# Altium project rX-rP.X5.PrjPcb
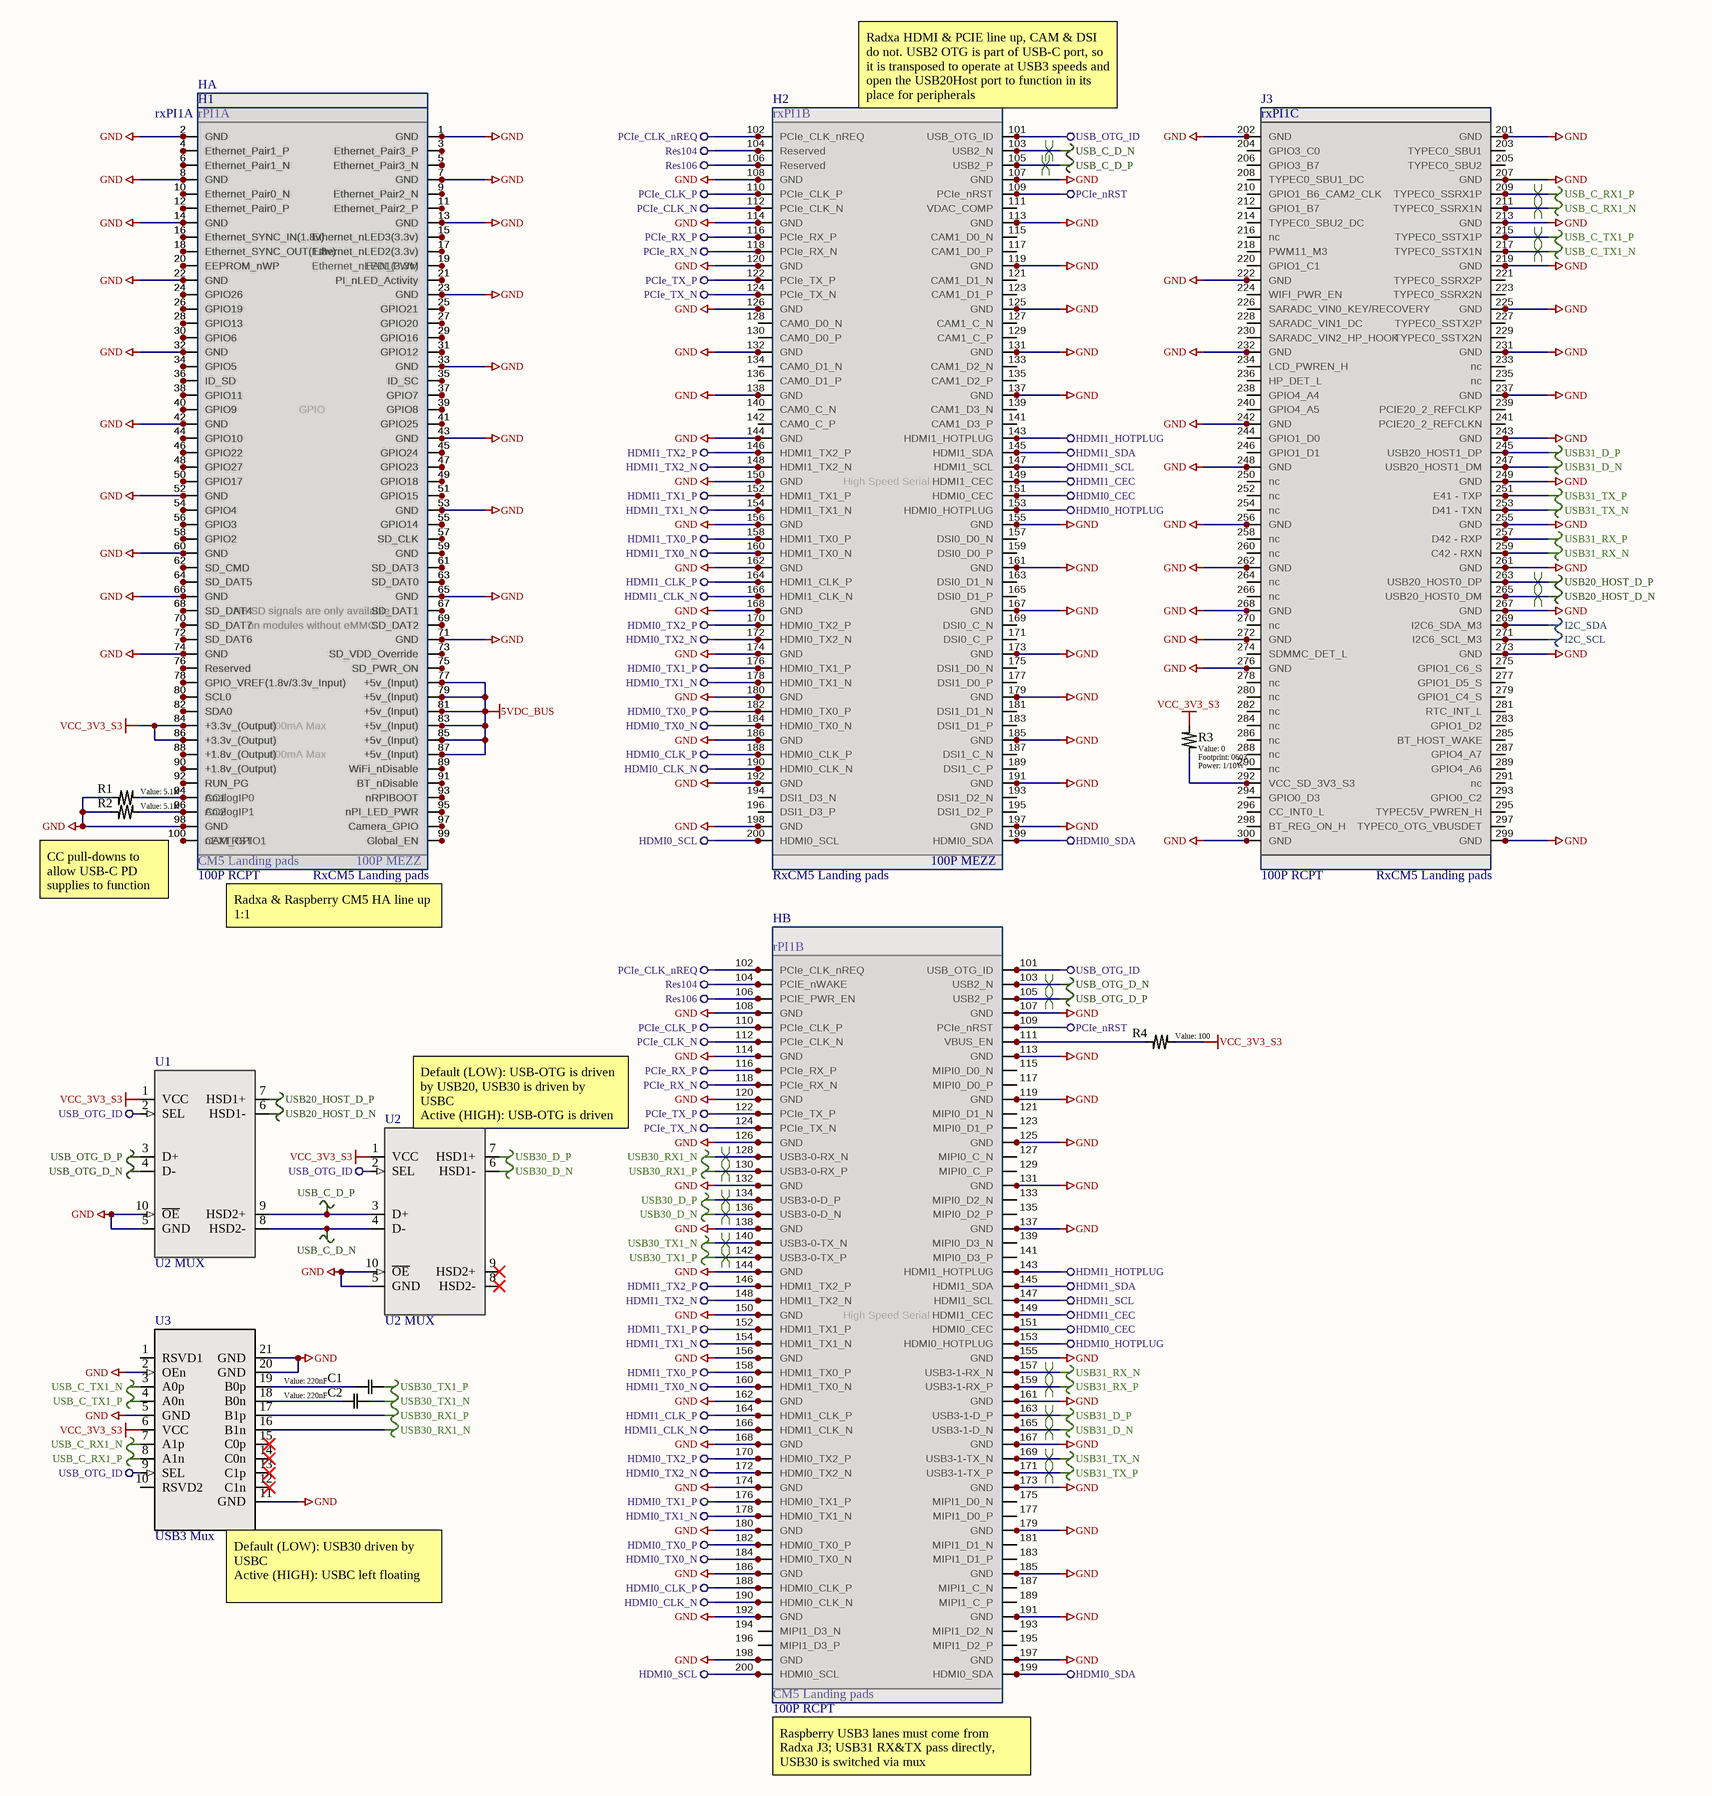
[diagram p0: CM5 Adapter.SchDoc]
1 sheet, 16 parts. Net scope: global (net labels, ports and power ports of the same name join across sheets).
Board file: CM5_Adapter.PcbDoc

## Sheet CM5 Adapter.SchDoc
size C; SheetNumber: 1; SheetTotal: 1

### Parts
C1  value 220nF  [0603]  (hidden comment: Generic Capacitor)
C2  value 220nF  [0603]  (hidden comment: Generic Capacitor)
H1  100P RCPT  [DF40C-100DS-0.4V(51)]
H2  100P MEZZ  [DF40C-100DS-0.4V(51)]
HA  100P MEZZ  [DF40C-100DP-0.4V(51)]
HB  100P RCPT  [DF40C-100DP-0.4V(51)]
J3  100P RCPT  [DF40C-100DS-0.4V(51)]
R1  value 5.1K  [0603]  (hidden comment: Generic Resistor)
R2  value 5.1K  [0603]  (hidden comment: Generic Resistor)
R3  value 0  Power: 1/10W  [0603]  (hidden comment: Generic Resistor)
R4  value 100  [0603]  (hidden comment: Generic Resistor)
rPI1  CM5 Landing pads  [rP-200P-CM-REP (top)]  (parts A,B of 2)
rxPI1  RxCM5 Landing pads  [RX-300P-CM-FTPD]  (parts A,B,C of 3)
U1  U2 MUX  [MSOP-10]
U2  U2 MUX  [MSOP-10]
U3  USB3 Mux  [QFN50P450X250X100-21N]

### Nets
5VDC_BUS: H1.77 H1.79 H1.81 H1.83 H1.85 H1.87 HA.78 HA.80 HA.82 HA.84 HA.86 HA.88 rPI1.77(+5v_(Input)) rPI1.79(+5v_(Input)) rPI1.81(+5v_(Input)) rPI1.83(+5v_(Input)) rPI1.85(+5v_(Input)) rPI1.87(+5v_(Input)) rxPI1.77(+5v_(Input)) rxPI1.79(+5v_(Input)) rxPI1.81(+5v_(Input)) rxPI1.83(+5v_(Input)) rxPI1.85(+5v_(Input)) rxPI1.87(+5v_(Input))
GND: H1.1 H1.2 H1.7 H1.8 H1.13 H1.14 H1.22 H1.23 H1.32 H1.33 H1.42 H1.43 H1.52 H1.53 H1.60 H1.65 H1.66 H1.71 H1.74 H1.98 H2.7 H2.8 H2.13 H2.14 H2.19 H2.20 H2.25 H2.26 H2.31 H2.32 H2.37 H2.38 H2.44 H2.50 H2.55 H2.56 H2.61 H2.62 H2.67 H2.68 H2.73 H2.74 H2.79 H2.80 H2.85 H2.86 H2.91 H2.92 H2.97 H2.98 HA.1 HA.2 HA.7 HA.8 HA.13 HA.14 HA.21 HA.24 HA.31 HA.34 HA.41 HA.44 HA.51 HA.54 HA.59 HA.65 HA.66 HA.72 HA.73 HA.97 HB.7 HB.8 HB.13 HB.14 HB.19 HB.20 HB.25 HB.26 HB.31 HB.32 HB.37 HB.38 HB.43 HB.49 HB.55 HB.56 HB.61 HB.62 HB.67 HB.68 HB.73 HB.74 HB.79 HB.80 HB.85 HB.86 HB.91 HB.92 HB.97 HB.98 J3.1 J3.2 J3.8 J3.14 J3.20 J3.21 J3.26 J3.31 J3.32 J3.38 J3.41 J3.44 J3.47 J3.50 J3.55 J3.56 J3.61 J3.62 J3.67 J3.68 J3.71 J3.74 J3.75 J3.99 J3.100 R1.2 R2.2 rPI1.1(GND) rPI1.2(GND) rPI1.7(GND) rPI1.8(GND) rPI1.13(GND) rPI1.14(GND) rPI1.22(GND) rPI1.23(GND) rPI1.32(GND) rPI1.33(GND) rPI1.42(GND) rPI1.43(GND) rPI1.52(GND) rPI1.53(GND) rPI1.60(GND) rPI1.65(GND) rPI1.66(GND) rPI1.71(GND) rPI1.74(GND) rPI1.98(GND) rPI1.107(GND) rPI1.108(GND) rPI1.113(GND) rPI1.114(GND) rPI1.119(GND) rPI1.120(GND) rPI1.125(GND) rPI1.126(GND) rPI1.131(GND) rPI1.132(GND) rPI1.137(GND) rPI1.138(GND) rPI1.144(GND) rPI1.150(GND) rPI1.155(GND) rPI1.156(GND) rPI1.161(GND) rPI1.162(GND) rPI1.167(GND) rPI1.168(GND) rPI1.173(GND) rPI1.174(GND) rPI1.179(GND) rPI1.180(GND) rPI1.185(GND) rPI1.186(GND) rPI1.191(GND) rPI1.192(GND) rPI1.197(GND) rPI1.198(GND) rxPI1.1(GND) rxPI1.2(GND) rxPI1.7(GND) rxPI1.8(GND) rxPI1.13(GND) rxPI1.14(GND) rxPI1.22(GND) rxPI1.23(GND) rxPI1.32(GND) rxPI1.33(GND) rxPI1.42(GND) rxPI1.43(GND) rxPI1.52(GND) rxPI1.53(GND) rxPI1.60(GND) rxPI1.65(GND) rxPI1.66(GND) rxPI1.71(GND) rxPI1.74(GND) rxPI1.98(GND) rxPI1.107(GND) rxPI1.108(GND) rxPI1.113(GND) rxPI1.114(GND) rxPI1.119(GND) rxPI1.120(GND) rxPI1.125(GND) rxPI1.126(GND) rxPI1.131(GND) rxPI1.132(GND) rxPI1.137(GND) rxPI1.138(GND) rxPI1.144(GND) rxPI1.150(GND) rxPI1.155(GND) rxPI1.156(GND) rxPI1.161(GND) rxPI1.162(GND) rxPI1.167(GND) rxPI1.168(GND) rxPI1.173(GND) rxPI1.174(GND) rxPI1.179(GND) rxPI1.180(GND) rxPI1.185(GND) rxPI1.186(GND) rxPI1.191(GND) rxPI1.192(GND) rxPI1.197(GND) rxPI1.198(GND) rxPI1.201(GND) rxPI1.202(GND) rxPI1.207(GND) rxPI1.213(GND) rxPI1.219(GND) rxPI1.222(GND) rxPI1.225(GND) rxPI1.231(GND) rxPI1.232(GND) rxPI1.237(GND) rxPI1.242(GND) rxPI1.243(GND) rxPI1.248(GND) rxPI1.249(GND) rxPI1.255(GND) rxPI1.256(GND) rxPI1.261(GND) rxPI1.262(GND) rxPI1.267(GND) rxPI1.268(GND) rxPI1.272(GND) rxPI1.273(GND) rxPI1.276(GND) rxPI1.299(GND) rxPI1.300(GND) U1.5(GND) U1.10(~{OE}) U2.5(GND) U2.10(~{OE}) U3.2(OEn) U3.5(GND) U3.11(GND) U3.20(GND) U3.21(GND)
HDMI0_CEC: H2.51 HB.52 rPI1.151(HDMI0_CEC) rxPI1.151(HDMI0_CEC)
HDMI0_CLK_N: H2.90 HB.89 rPI1.190(HDMI0_CLK_N) rxPI1.190(HDMI0_CLK_N)
HDMI0_CLK_P: H2.88 HB.87 rPI1.188(HDMI0_CLK_P) rxPI1.188(HDMI0_CLK_P)
HDMI0_HOTPLUG: H2.53 HB.54 rPI1.153(HDMI0_HOTPLUG) rxPI1.153(HDMI0_HOTPLUG)
HDMI0_SCL: H2.100 HB.99 rPI1.200(HDMI0_SCL) rxPI1.200(HDMI0_SCL)
HDMI0_SDA: H2.99 HB.100 rPI1.199(HDMI0_SDA) rxPI1.199(HDMI0_SDA)
HDMI0_TX0_N: H2.84 HB.83 rPI1.184(HDMI0_TX0_N) rxPI1.184(HDMI0_TX0_N)
HDMI0_TX0_P: H2.82 HB.81 rPI1.182(HDMI0_TX0_P) rxPI1.182(HDMI0_TX0_P)
HDMI0_TX1_N: H2.78 HB.77 rPI1.178(HDMI0_TX1_N) rxPI1.178(HDMI0_TX1_N)
HDMI0_TX1_P: H2.76 HB.75 rPI1.176(HDMI0_TX1_P) rxPI1.176(HDMI0_TX1_P)
HDMI0_TX2_N: H2.72 HB.71 rPI1.172(HDMI0_TX2_N) rxPI1.172(HDMI0_TX2_N)
HDMI0_TX2_P: H2.70 HB.69 rPI1.170(HDMI0_TX2_P) rxPI1.170(HDMI0_TX2_P)
HDMI1_CEC: H2.49 HB.50 rPI1.149(HDMI1_CEC) rxPI1.149(HDMI1_CEC)
HDMI1_CLK_N: H2.66 HB.65 rPI1.166(HDMI1_CLK_N) rxPI1.166(HDMI1_CLK_N)
HDMI1_CLK_P: H2.64 HB.63 rPI1.164(HDMI1_CLK_P) rxPI1.164(HDMI1_CLK_P)
HDMI1_HOTPLUG: H2.43 HB.44 rPI1.143(HDMI1_HOTPLUG) rxPI1.143(HDMI1_HOTPLUG)
HDMI1_SCL: H2.47 HB.48 rPI1.147(HDMI1_SCL) rxPI1.147(HDMI1_SCL)
HDMI1_SDA: H2.45 HB.46 rPI1.145(HDMI1_SDA) rxPI1.145(HDMI1_SDA)
HDMI1_TX0_N: H2.60 HB.59 rPI1.160(HDMI1_TX0_N) rxPI1.160(HDMI1_TX0_N)
HDMI1_TX0_P: H2.58 HB.57 rPI1.158(HDMI1_TX0_P) rxPI1.158(HDMI1_TX0_P)
HDMI1_TX1_N: H2.54 HB.53 rPI1.154(HDMI1_TX1_N) rxPI1.154(HDMI1_TX1_N)
HDMI1_TX1_P: H2.52 HB.51 rPI1.152(HDMI1_TX1_P) rxPI1.152(HDMI1_TX1_P)
HDMI1_TX2_N: H2.48 HB.47 rPI1.148(HDMI1_TX2_N) rxPI1.148(HDMI1_TX2_N)
HDMI1_TX2_P: H2.46 HB.45 rPI1.146(HDMI1_TX2_P) rxPI1.146(HDMI1_TX2_P)
I2C_SCL: J3.72 rxPI1.271(I2C6_SCL_M3)
I2C_SDA: J3.70 rxPI1.269(I2C6_SDA_M3)
PCIe_CLK_N: H2.12 HB.11 rPI1.112(PCIe_CLK_N) rxPI1.112(PCIe_CLK_N)
PCIe_CLK_nREQ: H2.2 HB.1 rPI1.102(PCIe_CLK_nREQ) rxPI1.102(PCIe_CLK_nREQ)
PCIe_CLK_P: H2.10 HB.9 rPI1.110(PCIe_CLK_P) rxPI1.110(PCIe_CLK_P)
PCIe_nRST: H2.9 HB.10 rPI1.109(PCIe_nRST) rxPI1.109(PCIe_nRST)
PCIe_RX_N: H2.18 HB.17 rPI1.118(PCIe_RX_N) rxPI1.118(PCIe_RX_N)
PCIe_RX_P: H2.16 HB.15 rPI1.116(PCIe_RX_P) rxPI1.116(PCIe_RX_P)
PCIe_TX_N: H2.24 HB.23 rPI1.124(PCIe_TX_N) rxPI1.124(PCIe_TX_N)
PCIe_TX_P: H2.22 HB.21 rPI1.122(PCIe_TX_P) rxPI1.122(PCIe_TX_P)
Res104: H2.4 HB.3 rPI1.104(PCIE_nWAKE) rxPI1.104(Reserved)
Res106: H2.6 HB.5 rPI1.106(PCIE_PWR_EN) rxPI1.106(Reserved)
USB20_HOST_D_N: J3.66 rxPI1.265(USB20_HOST0_DM) U1.6(HSD1-)
USB20_HOST_D_P: J3.64 rxPI1.263(USB20_HOST0_DP) U1.7(HSD1+)
USB30_D_N: HB.35 rPI1.136(USB3-0-D_N) U2.6(HSD1-)
USB30_D_P: HB.33 rPI1.134(USB3-0-D_P) U2.7(HSD1+)
USB30_RX1_N: HB.27 rPI1.128(USB3-0-RX_N) U3.16(B1n)
USB30_RX1_P: HB.29 rPI1.130(USB3-0-RX_P) U3.17(B1p)
USB30_TX1_N: C2.2 HB.39 rPI1.140(USB3-0-TX_N)
USB30_TX1_P: C1.2 HB.41 rPI1.142(USB3-0-TX_P)
USB31_D_N: HB.66 J3.48 rPI1.165(USB3-1-D_N) rxPI1.247(USB20_HOST1_DM)
USB31_D_P: HB.64 J3.46 rPI1.163(USB3-1-D_P) rxPI1.245(USB20_HOST1_DP)
USB31_RX_N: HB.58 J3.60 rPI1.157(USB3-1-RX_N) rxPI1.259(C42_-_RXN)
USB31_RX_P: HB.60 J3.58 rPI1.159(USB3-1-RX_P) rxPI1.257(D42_-_RXP)
USB31_TX_N: HB.70 J3.54 rPI1.169(USB3-1-TX_N) rxPI1.253(D41_-_TXN)
USB31_TX_P: HB.72 J3.52 rPI1.171(USB3-1-TX_P) rxPI1.251(E41_-_TXP)
USB_C_D_N: H2.3 rxPI1.103(USB2_N) U1.8(HSD2-) U2.4(D-)
USB_C_D_P: H2.5 rxPI1.105(USB2_P) U1.9(HSD2+) U2.3(D+)
USB_C_RX1_N: J3.12 rxPI1.211(TYPEC0_SSRX1N) U3.7(A1p)
USB_C_RX1_P: J3.10 rxPI1.209(TYPEC0_SSRX1P) U3.8(A1n)
USB_C_TX1_N: J3.18 rxPI1.217(TYPEC0_SSTX1N) U3.3(A0p)
USB_C_TX1_P: J3.16 rxPI1.215(TYPEC0_SSTX1P) U3.4(A0n)
USB_OTG_D_N: HB.4 rPI1.103(USB2_N) U1.4(D-)
USB_OTG_D_P: HB.6 rPI1.105(USB2_P) U1.3(D+)
USB_OTG_ID: H2.1 HB.2 rPI1.101(USB_OTG_ID) rxPI1.101(USB_OTG_ID) U1.2(SEL) U2.2(SEL) U3.9(SEL)
VCC_3V3_S3: H1.84 H1.86 HA.83 HA.85 R3.1 R4.1 rPI1.84(+3.3v_(Output)) rPI1.86(+3.3v_(Output)) rxPI1.84(+3.3v_(Output)) rxPI1.86(+3.3v_(Output)) U1.1(VCC) U2.1(VCC) U3.6(VCC)
NetC1_1: C1.1 U3.19(B0p)
NetC2_1: C2.1 U3.18(B0n)
NetH1_3: H1.3 HA.4 rPI1.3(Ethernet_Pair3_P) rxPI1.3(Ethernet_Pair3_P)
NetH1_4: H1.4 HA.3 rPI1.4(Ethernet_Pair1_P) rxPI1.4(Ethernet_Pair1_P)
NetH1_5: H1.5 HA.6 rPI1.5(Ethernet_Pair3_N) rxPI1.5(Ethernet_Pair3_N)
NetH1_6: H1.6 HA.5 rPI1.6(Ethernet_Pair1_N) rxPI1.6(Ethernet_Pair1_N)
NetH1_9: H1.9 HA.10 rPI1.9(Ethernet_Pair2_N) rxPI1.9(Ethernet_Pair2_N)
NetH1_10: H1.10 HA.9 rPI1.10(Ethernet_Pair0_N) rxPI1.10(Ethernet_Pair0_N)
NetH1_11: H1.11 HA.12 rPI1.11(Ethernet_Pair2_P) rxPI1.11(Ethernet_Pair2_P)
NetH1_12: H1.12 HA.11 rPI1.12(Ethernet_Pair0_P) rxPI1.12(Ethernet_Pair0_P)
NetH1_15: H1.15 HA.16 rPI1.15(Ethernet_nLED3(3.3v)) rxPI1.15(Ethernet_nLED3(3.3v))
NetH1_16: H1.16 HA.15 rPI1.16(Ethernet_SYNC_IN(1.8v)) rxPI1.16(Ethernet_SYNC_IN(1.8v))
NetH1_17: H1.17 HA.18 rPI1.17(Ethernet_nLED2(3.3v)) rxPI1.17(Ethernet_nLED2(3.3v))
NetH1_18: H1.18 HA.17 rPI1.18(Ethernet_SYNC_OUT(1.8v)) rxPI1.18(Ethernet_SYNC_OUT(1.8v))
NetH1_19: H1.19 HA.20 rPI1.19(FAN_PWM) rxPI1.19(Ethernet_nLED1(3.3v))
NetH1_20: H1.20 HA.19 rPI1.20(EEPROM_nWP) rxPI1.20(EEPROM_nWP)
NetH1_21: H1.21 HA.22 rPI1.21(PI_nLED_Activity) rxPI1.21(PI_nLED_Activity)
NetH1_24: H1.24 HA.23 rPI1.24(GPIO26) rxPI1.24(GPIO26)
NetH1_25: H1.25 HA.26 rPI1.25(GPIO21) rxPI1.25(GPIO21)
NetH1_26: H1.26 HA.25 rPI1.26(GPIO19) rxPI1.26(GPIO19)
NetH1_27: H1.27 HA.28 rPI1.27(GPIO20) rxPI1.27(GPIO20)
NetH1_28: H1.28 HA.27 rPI1.28(GPIO13) rxPI1.28(GPIO13)
NetH1_29: H1.29 HA.30 rPI1.29(GPIO16) rxPI1.29(GPIO16)
NetH1_30: H1.30 HA.29 rPI1.30(GPIO6) rxPI1.30(GPIO6)
NetH1_31: H1.31 HA.32 rPI1.31(GPIO12) rxPI1.31(GPIO12)
NetH1_34: H1.34 HA.33 rPI1.34(GPIO5) rxPI1.34(GPIO5)
NetH1_35: H1.35 HA.36 rPI1.35(ID_SC) rxPI1.35(ID_SC)
NetH1_36: H1.36 HA.35 rPI1.36(ID_SD) rxPI1.36(ID_SD)
NetH1_37: H1.37 HA.38 rPI1.37(GPIO7) rxPI1.37(GPIO7)
NetH1_38: H1.38 HA.37 rPI1.38(GPIO11) rxPI1.38(GPIO11)
NetH1_39: H1.39 HA.40 rPI1.39(GPIO8) rxPI1.39(GPIO8)
NetH1_40: H1.40 HA.39 rPI1.40(GPIO9) rxPI1.40(GPIO9)
NetH1_41: H1.41 HA.42 rPI1.41(GPIO25) rxPI1.41(GPIO25)
NetH1_44: H1.44 HA.43 rPI1.44(GPIO10) rxPI1.44(GPIO10)
NetH1_45: H1.45 HA.46 rPI1.45(GPIO24) rxPI1.45(GPIO24)
NetH1_46: H1.46 HA.45 rPI1.46(GPIO22) rxPI1.46(GPIO22)
NetH1_47: H1.47 HA.48 rPI1.47(GPIO23) rxPI1.47(GPIO23)
NetH1_48: H1.48 HA.47 rPI1.48(GPIO27) rxPI1.48(GPIO27)
NetH1_49: H1.49 HA.50 rPI1.49(GPIO18) rxPI1.49(GPIO18)
NetH1_50: H1.50 HA.49 rPI1.50(GPIO17) rxPI1.50(GPIO17)
NetH1_51: H1.51 HA.52 rPI1.51(GPIO15) rxPI1.51(GPIO15)
NetH1_54: H1.54 HA.53 rPI1.54(GPIO4) rxPI1.54(GPIO4)
NetH1_55: H1.55 HA.56 rPI1.55(GPIO14) rxPI1.55(GPIO14)
NetH1_56: H1.56 HA.55 rPI1.56(GPIO3) rxPI1.56(GPIO3)
NetH1_57: H1.57 HA.58 rPI1.57(SD_CLK) rxPI1.57(SD_CLK)
NetH1_58: H1.58 HA.57 rPI1.58(GPIO2) rxPI1.58(GPIO2)
NetH1_59: H1.59 HA.60 rPI1.59(GND) rxPI1.59(GND)
NetH1_61: H1.61 HA.62 rPI1.61(SD_DAT3) rxPI1.61(SD_DAT3)
NetH1_62: H1.62 HA.61 rPI1.62(SD_CMD) rxPI1.62(SD_CMD)
NetH1_63: H1.63 HA.64 rPI1.63(SD_DAT0) rxPI1.63(SD_DAT0)
NetH1_64: H1.64 HA.63 rPI1.64(SD_DAT5) rxPI1.64(SD_DAT5)
NetH1_67: H1.67 HA.68 rPI1.67(SD_DAT1) rxPI1.67(SD_DAT1)
NetH1_68: H1.68 HA.67 rPI1.68(SD_DAT4) rxPI1.68(SD_DAT4)
NetH1_69: H1.69 HA.70 rPI1.69(SD_DAT2) rxPI1.69(SD_DAT2)
NetH1_70: H1.70 HA.69 rPI1.70(SD_DAT7) rxPI1.70(SD_DAT7)
NetH1_72: H1.72 HA.71 rPI1.72(SD_DAT6) rxPI1.72(SD_DAT6)
NetH1_73: H1.73 HA.74 rPI1.73(SD_VDD_Override) rxPI1.73(SD_VDD_Override)
NetH1_75: H1.75 HA.76 rPI1.75(SD_PWR_ON) rxPI1.75(SD_PWR_ON)
NetH1_76: H1.76 HA.75 rPI1.76(Reserved) rxPI1.76(Reserved)
NetH1_78: H1.78 HA.77 rPI1.78(GPIO_VREF(1.8v/3.3v_Input)) rxPI1.78(GPIO_VREF(1.8v/3.3v_Input))
NetH1_80: H1.80 HA.79 rPI1.80(SCL0) rxPI1.80(SCL0)
NetH1_82: H1.82 HA.81 rPI1.82(SDA0) rxPI1.82(SDA0)
NetH1_88: H1.88 HA.87 rPI1.88(+1.8v_(Output)) rxPI1.88(+1.8v_(Output))
NetH1_89: H1.89 HA.90 rPI1.89(WiFi_nDisable) rxPI1.89(WiFi_nDisable)
NetH1_90: H1.90 HA.89 rPI1.90(+1.8v_(Output)) rxPI1.90(+1.8v_(Output))
NetH1_91: H1.91 HA.92 rPI1.91(BT_nDisable) rxPI1.91(BT_nDisable)
NetH1_92: H1.92 HA.91 rPI1.92(RUN_PG) rxPI1.92(RUN_PG)
NetH1_93: H1.93 HA.94 rPI1.93(nRPIBOOT) rxPI1.93(nRPIBOOT)
NetH1_94: H1.94 HA.93 R1.1 rPI1.94(CC1) rxPI1.94(AnalogIP0)
NetH1_95: H1.95 HA.96 rPI1.95(nPI_LED_PWR) rxPI1.95(nPI_LED_PWR)
NetH1_96: H1.96 HA.95 R2.1 rPI1.96(CC2) rxPI1.96(AnalogIP1)
NetH1_97: H1.97 HA.98 rPI1.97(Camera_GPIO) rxPI1.97(Camera_GPIO)
NetH1_99: H1.99 HA.100 rPI1.99(Global_EN) rxPI1.99(Global_EN)
NetH1_100: H1.100 HA.99 rPI1.100(CAM_GPIO1) rxPI1.100(nEXTRST)
NetH2_11: H2.11 rxPI1.111(VDAC_COMP)
NetH2_15: H2.15 rxPI1.115(CAM1_D0_N)
NetH2_17: H2.17 rxPI1.117(CAM1_D0_P)
NetH2_21: H2.21 rxPI1.121(CAM1_D1_N)
NetH2_23: H2.23 rxPI1.123(CAM1_D1_P)
NetH2_27: H2.27 rxPI1.127(CAM1_C_N)
NetH2_28: H2.28 rxPI1.128(CAM0_D0_N)
NetH2_29: H2.29 rxPI1.129(CAM1_C_P)
NetH2_30: H2.30 rxPI1.130(CAM0_D0_P)
NetH2_33: H2.33 rxPI1.133(CAM1_D2_N)
NetH2_34: H2.34 rxPI1.134(CAM0_D1_N)
NetH2_35: H2.35 rxPI1.135(CAM1_D2_P)
NetH2_36: H2.36 rxPI1.136(CAM0_D1_P)
NetH2_39: H2.39 rxPI1.139(CAM1_D3_N)
NetH2_40: H2.40 rxPI1.140(CAM0_C_N)
NetH2_41: H2.41 rxPI1.141(CAM1_D3_P)
NetH2_42: H2.42 rxPI1.142(CAM0_C_P)
NetH2_57: H2.57 rxPI1.157(DSI0_D0_N)
NetH2_59: H2.59 rxPI1.159(DSI0_D0_P)
NetH2_63: H2.63 rxPI1.163(DSI0_D1_N)
NetH2_65: H2.65 rxPI1.165(DSI0_D1_P)
NetH2_69: H2.69 rxPI1.169(DSI0_C_N)
NetH2_71: H2.71 rxPI1.171(DSI0_C_P)
NetH2_75: H2.75 rxPI1.175(DSI1_D0_N)
NetH2_77: H2.77 rxPI1.177(DSI1_D0_P)
NetH2_81: H2.81 rxPI1.181(DSI1_D1_N)
NetH2_83: H2.83 rxPI1.183(DSI1_D1_P)
NetH2_87: H2.87 rxPI1.187(DSI1_C_N)
NetH2_89: H2.89 rxPI1.189(DSI1_C_P)
NetH2_93: H2.93 rxPI1.193(DSI1_D2_N)
NetH2_94: H2.94 rxPI1.194(DSI1_D3_N)
NetH2_95: H2.95 rxPI1.195(DSI1_D2_P)
NetH2_96: H2.96 rxPI1.196(DSI1_D3_P)
NetHB_12: HB.12 R4.2 rPI1.111(VBUS_EN)
NetHB_16: HB.16 rPI1.115(MIPI0_D0_N)
NetHB_18: HB.18 rPI1.117(MIPI0_D0_P)
NetHB_22: HB.22 rPI1.121(MIPI0_D1_N)
NetHB_24: HB.24 rPI1.123(MIPI0_D1_P)
NetHB_28: HB.28 rPI1.127(MIPI0_C_N)
NetHB_30: HB.30 rPI1.129(MIPI0_C_P)
NetHB_34: HB.34 rPI1.133(MIPI0_D2_N)
NetHB_36: HB.36 rPI1.135(MIPI0_D2_P)
NetHB_40: HB.40 rPI1.139(MIPI0_D3_N)
NetHB_42: HB.42 rPI1.141(MIPI0_D3_P)
NetHB_76: HB.76 rPI1.175(MIPI1_D0_N)
NetHB_78: HB.78 rPI1.177(MIPI1_D0_P)
NetHB_82: HB.82 rPI1.181(MIPI1_D1_N)
NetHB_84: HB.84 rPI1.183(MIPI1_D1_P)
NetHB_88: HB.88 rPI1.187(MIPI1_C_N)
NetHB_90: HB.90 rPI1.189(MIPI1_C_P)
NetHB_93: HB.93 rPI1.194(MIPI1_D3_N)
NetHB_94: HB.94 rPI1.193(MIPI1_D2_N)
NetHB_95: HB.95 rPI1.196(MIPI1_D3_P)
NetHB_96: HB.96 rPI1.195(MIPI1_D2_P)
NetJ3_3: J3.3 rxPI1.204(GPIO3_C0)
NetJ3_4: J3.4 rxPI1.203(TYPEC0_SBU1)
NetJ3_5: J3.5 rxPI1.206(GPIO3_B7)
NetJ3_6: J3.6 rxPI1.205(TYPEC0_SBU2)
NetJ3_7: J3.7 rxPI1.208(TYPEC0_SBU1_DC)
NetJ3_9: J3.9 rxPI1.210(GPIO1_B6_CAM2_CLK)
NetJ3_11: J3.11 rxPI1.212(GPIO1_B7)
NetJ3_13: J3.13 rxPI1.214(TYPEC0_SBU2_DC)
NetJ3_15: J3.15 rxPI1.216(nc)
NetJ3_17: J3.17 rxPI1.218(PWM11_M3)
NetJ3_19: J3.19 rxPI1.220(GPIO1_C1)
NetJ3_22: J3.22 rxPI1.221(TYPEC0_SSRX2P)
NetJ3_23: J3.23 rxPI1.224(WIFI_PWR_EN)
NetJ3_24: J3.24 rxPI1.223(TYPEC0_SSRX2N)
NetJ3_25: J3.25 rxPI1.226(SARADC_VIN0_KEY/RECOVERY)
NetJ3_27: J3.27 rxPI1.228(SARADC_VIN1_DC)
NetJ3_28: J3.28 rxPI1.227(TYPEC0_SSTX2P)
NetJ3_29: J3.29 rxPI1.230(SARADC_VIN2_HP_HOOK)
NetJ3_30: J3.30 rxPI1.229(TYPEC0_SSTX2N)
NetJ3_33: J3.33 rxPI1.234(LCD_PWREN_H)
NetJ3_34: J3.34 rxPI1.233(nc)
NetJ3_35: J3.35 rxPI1.236(HP_DET_L)
NetJ3_36: J3.36 rxPI1.235(nc)
NetJ3_37: J3.37 rxPI1.238(GPIO4_A4)
NetJ3_39: J3.39 rxPI1.240(GPIO4_A5)
NetJ3_40: J3.40 rxPI1.239(PCIE20_2_REFCLKP)
NetJ3_42: J3.42 rxPI1.241(PCIE20_2_REFCLKN)
NetJ3_43: J3.43 rxPI1.244(GPIO1_D0)
NetJ3_45: J3.45 rxPI1.246(GPIO1_D1)
NetJ3_49: J3.49 rxPI1.250(nc)
NetJ3_51: J3.51 rxPI1.252(nc)
NetJ3_53: J3.53 rxPI1.254(nc)
NetJ3_57: J3.57 rxPI1.258(nc)
NetJ3_59: J3.59 rxPI1.260(nc)
NetJ3_63: J3.63 rxPI1.264(nc)
NetJ3_65: J3.65 rxPI1.266(nc)
NetJ3_69: J3.69 rxPI1.270(nc)
NetJ3_73: J3.73 rxPI1.274(SDMMC_DET_L)
NetJ3_76: J3.76 rxPI1.275(GPIO1_C6_S)
NetJ3_77: J3.77 rxPI1.278(nc)
NetJ3_78: J3.78 rxPI1.277(GPIO1_D5_S)
NetJ3_79: J3.79 rxPI1.280(nc)
NetJ3_80: J3.80 rxPI1.279(GPIO1_C4_S)
NetJ3_81: J3.81 rxPI1.282(nc)
NetJ3_82: J3.82 rxPI1.281(RTC_INT_L)
NetJ3_83: J3.83 rxPI1.284(nc)
NetJ3_84: J3.84 rxPI1.283(GPIO1_D2)
NetJ3_85: J3.85 rxPI1.286(nc)
NetJ3_86: J3.86 rxPI1.285(BT_HOST_WAKE)
NetJ3_87: J3.87 rxPI1.288(nc)
NetJ3_88: J3.88 rxPI1.287(GPIO4_A7)
NetJ3_89: J3.89 rxPI1.290(nc)
NetJ3_90: J3.90 rxPI1.289(GPIO4_A6)
NetJ3_91: J3.91 R3.2 rxPI1.292(VCC_SD_3V3_S3)
NetJ3_92: J3.92 rxPI1.291(nc)
NetJ3_93: J3.93 rxPI1.294(GPIO0_D3)
NetJ3_94: J3.94 rxPI1.293(GPIO0_C2)
NetJ3_95: J3.95 rxPI1.296(CC_INT0_L)
NetJ3_96: J3.96 rxPI1.295(TYPEC5V_PWREN_H)
NetJ3_97: J3.97 rxPI1.298(BT_REG_ON_H)
NetJ3_98: J3.98 rxPI1.297(TYPEC0_OTG_VBUSDET)

Not connected (* = marked no-connect by the designer): U2 8(HSD2-)* 9(HSD2+)*; U3 1(RSVD1) 10(RSVD2) 12(C1n)* 13(C1p)* 14(C0n)* 15(C0p)*

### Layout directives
differential pair: USB20_HOST_D_N, USB20_HOST_D_P, USB30_D_N, USB30_D_P, USB30_RX1_N, USB30_RX1_P, USB30_TX1_N, USB30_TX1_P, USB31_D_N, USB31_D_P, USB31_RX_N, USB31_RX_P, USB31_TX_N, USB31_TX_P, USB_C_D_N, USB_C_D_P, USB_C_RX1_N, USB_C_RX1_P, USB_C_TX1_N, USB_C_TX1_P, USB_OTG_D_N, USB_OTG_D_P

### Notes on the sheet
- Radxa HDMI & PCIE line up, CAM & DSI do not. USB2 OTG is part of USB-C port, so it is transposed to operate at USB3 speeds and open the USB20Host port to function in its place for peripherals
- CC pull-downs to allow USB-C PD supplies to function
- Radxa & Raspberry CM5 HA line up 1:1
- (near U2) Default (LOW): USB-OTG is driven by USB20, USB30 is driven by USBC
  Active (HIGH): USB-OTG is driven by USB-C, USB20 left floating
- (near U3) Default (LOW): USB30 driven by USBC
  Active (HIGH): USBC left floating
- Raspberry USB3 lanes must come from Radxa J3; USB31 RX&TX pass directly, USB30 is switched via mux

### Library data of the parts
C1 C2 = Generic Capacitor: Voltage: >10V; Tolerance: 10%
H1 H2 J3 = DF40-100DS RCPT_1: 100 Position Connector Receptacle, Center Strip Contacts Surface Mount Gold; MF: Hirose
HA HB = DF40-XX-100DS RCPT: 100 Position Connector Receptacle, Center Strip Contacts Surface Mount Gold; MF: Hirose; MP: DF40C-100DS-0.4V(51)
R1 R2 R4 = Generic Resistor: Tolerance: 1%; Power: 1/10W
R3 = Generic Resistor: Tolerance: 1%
rPI1 = RP-CM5-Rep: Compute Module 5 adapter Footprint / Overlap Hirose 100P connector over pads to place actual components
rxPI1 = RX-CM5: Radxa Compute Module 5 Footprint / Overlap Hirose 100P connector over pads to place actual components
U1 U2 = FSUSB42MUX: FSUSB42 Series DPDT 4.3 V 480 Mbps SMT Hi Speed USB 2.0 Switch - MSOP-10; MF: ON Semiconductor
U3 = TMUXHS4212IRKSR: 2-channel 16-Gbps 2:1/1:2 differential mux/demux; Mfr_Name: Texas Instruments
